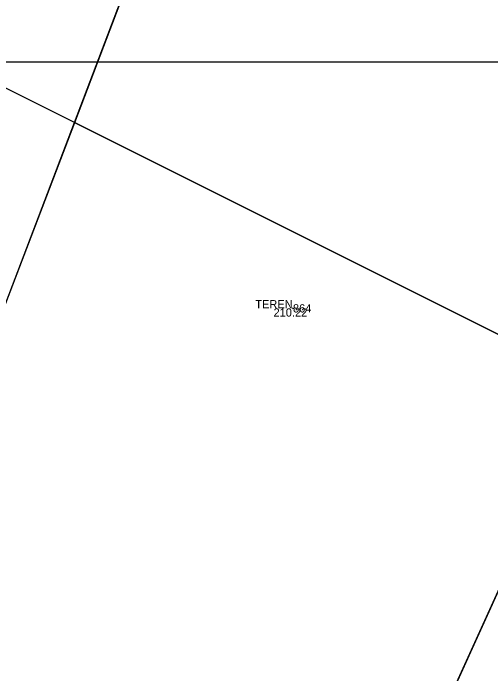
# Model space of a CAD drawing. Extents: x -263091 to -262565, y -1238731 to -1237092.
# Drawn here: x -262809.83 to -262798.24, y -1237679.73 to -1237663.71 of the extents above; entities that cross this region are included whole.
import ezdxf

# ---------------------------------------------------------------- set-up
doc = ezdxf.new("R2010")
doc.units = 0
for name, color, linetype in [('02_Oplotenie', 7, 'Continuous'), ('10', 7, 'Continuous'), ('11_Hranica_KN', 7, 'Continuous'), ('Groma (21)', 7, 'Continuous'), ('Groma (22)', 7, 'Continuous'), ('Groma (23)', 7, 'Continuous'), ('Groma (24)', 7, 'Continuous'), ('U004_Zeleň_mimo', 7, 'Continuous'), ('U004_Zeleň_vnútro', 7, 'Continuous'), ('U005_Zeleň_mimo', 7, 'Continuous'), ('Vrstva 51', 7, 'Continuous')]:
    doc.layers.add(name, color=color, linetype=linetype)

msp = doc.modelspace()

# ---------------------------------------------------------------- linework, layer by layer
at = {"layer": '02_Oplotenie'}
msp.add_lwpolyline([(-262834.343, -1237921.203), (-262834.024, -1237915.302), (-262833.812, -1237906.279), (-262832.732, -1237884.616), (-262831.151, -1237869.343), (-262829.251, -1237856.325), (-262826.951, -1237845.31), (-262823.094, -1237827.731), (-262817.951, -1237804.339), (-262814.023, -1237784.135), (-262812.336, -1237767.05), (-262811.754, -1237744.594), (-262811.555, -1237719.093), (-262809.863, -1237708.888), (-262807.835, -1237700.632), (-262803.244, -1237689.13), (-262797.291, -1237676.038)], dxfattribs=at)
at = {"layer": '10'}
msp.add_lwpolyline([(-262813.033, -1237664.011), (-262780.925, -1237680.054), (-262777.93, -1237681.41), (-262750.961, -1237695.025)], dxfattribs=at)
at = {"layer": '11_Hranica_KN'}
for points in [[(-262808.336, -1237666.357), (-262793.39, -1237627.04), (-262791.777, -1237622.951)], [(-262860.57, -1237917.21), (-262859.39, -1237895.81), (-262865.89, -1237895.46), (-262864.07, -1237848.35), (-262863.848, -1237844.551), (-262854.69, -1237845.12), (-262848.93, -1237845.467), (-262849.15, -1237849.66), (-262837.88, -1237850.32), (-262835.06, -1237803.04), (-262846.51, -1237802.23), (-262851.357, -1237801.851), (-262850.83, -1237794.01), (-262846.699, -1237756.584), (-262841.32, -1237757.58), (-262829.89, -1237759.64), (-262821.36, -1237713.08), (-262832.88, -1237711.03), (-262837.415, -1237710.153), (-262826.672, -1237665.044), (-262821.31, -1237667.32), (-262810.29, -1237671.46), (-262808.336, -1237666.357)]]:
    msp.add_lwpolyline(points, dxfattribs=at)
at = {"layer": 'Groma (21)'}
msp.add_circle((-262803.038, -1237670.866), 0.01, dxfattribs=at)
at = {"layer": 'U004_Zeleň_mimo'}
msp.add_lwpolyline([(-262829.89, -1237759.64), (-262821.36, -1237713.08), (-262832.88, -1237711.03), (-262837.42, -1237710.15), (-262826.67, -1237665.04), (-262821.31, -1237667.32), (-262810.29, -1237671.46), (-262808.34, -1237666.36), (-262795.54, -1237672.75), (-262797.29, -1237676.04), (-262803.24, -1237689.13), (-262807.84, -1237700.63), (-262809.86, -1237708.89), (-262811.56, -1237719.09), (-262811.75, -1237744.59)], dxfattribs=at)
at = {"layer": 'U004_Zeleň_vnútro'}
msp.add_lwpolyline([(-262811.75, -1237744.59), (-262811.56, -1237719.09), (-262809.86, -1237708.89), (-262807.84, -1237700.63), (-262803.24, -1237689.13), (-262797.29, -1237676.04), (-262795.54, -1237672.75), (-262794.83, -1237673.1), (-262795.49, -1237674.5), (-262796.13, -1237674.77), (-262796.37, -1237675.19), (-262796.04, -1237675.47), (-262802.31, -1237689.3), (-262806.91, -1237700.93), (-262808.86, -1237708.99), (-262810.49, -1237719.25), (-262810.65, -1237744.37)], dxfattribs=at)
msp.add_lwpolyline([(-262811.75, -1237744.59), (-262811.56, -1237719.09), (-262809.86, -1237708.89), (-262807.84, -1237700.63), (-262803.24, -1237689.13), (-262797.29, -1237676.04), (-262795.54, -1237672.75), (-262794.83, -1237673.1), (-262795.49, -1237674.5), (-262796.13, -1237674.77), (-262796.37, -1237675.19), (-262796.04, -1237675.47), (-262802.31, -1237689.3), (-262806.91, -1237700.93), (-262808.86, -1237708.99), (-262810.49, -1237719.25), (-262810.65, -1237744.37)], dxfattribs=at)
at = {"layer": 'U005_Zeleň_mimo'}
msp.add_lwpolyline([(-262747.68, -1237500.55), (-262747.82, -1237524.57), (-262747.79, -1237545.2), (-262748.22, -1237555.41), (-262749.02, -1237564.32), (-262749.97, -1237571.23), (-262751.77, -1237579.93), (-262754.83, -1237588.44), (-262759.49, -1237598.41), (-262767.84, -1237616), (-262778.34, -1237638.1), (-262786.05, -1237653.78), (-262793.97, -1237669.78), (-262795.54, -1237672.75), (-262808.34, -1237666.36), (-262793.39, -1237627.04), (-262791.78, -1237622.95), (-262787.11, -1237623.75), (-262784.13, -1237624.4), (-262781.33, -1237608.15), (-262778.14, -1237587.84), (-262773.94, -1237562.14), (-262768.34, -1237527.64), (-262757.02, -1237455.96)], dxfattribs=at)
at = {"layer": 'Vrstva 51'}
msp.add_lwpolyline([(-262609.436, -1238258.884), (-263029.436, -1238258.884), (-263029.436, -1237664.884), (-262609.436, -1237664.884)], close=True, dxfattribs=at)

# ---------------------------------------------------------------- texts
at = {"layer": 'Groma (22)'}
msp.add_text('864', height=0.2, dxfattribs=at).set_placement((-262803.038, -1237670.966))
at = {"layer": 'Groma (23)'}
msp.add_text('210.22', height=0.2, dxfattribs=at).set_placement((-262803.511, -1237671.066))
at = {"layer": 'Groma (24)'}
msp.add_text('TEREN', height=0.2, dxfattribs=at).set_placement((-262803.953, -1237670.866))

doc.saveas('drawing.dxf')
